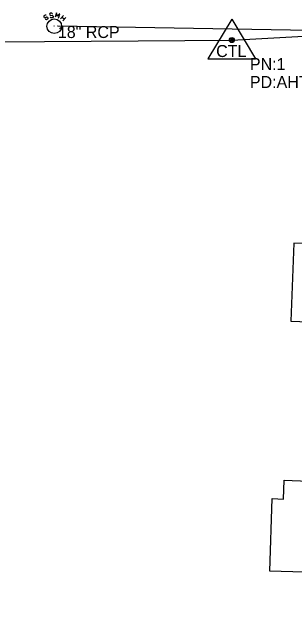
# Model space of a CAD drawing. Extents: x 1304270 to 1306561, y 1876019 to 1876752.
# Drawn here: x 1304782.1 to 1304900.2, y 1876151.4 to 1876403.7 of the extents above; entities that cross this region are included whole.
import ezdxf

# ---------------------------------------------------------------- set-up
doc = ezdxf.new("R2010")
doc.units = 0
for name, color, linetype in [('Default', 7, 'Continuous'), ('S_BUILDING', 7, 'Continuous'), ('S_PRIMARY_CTL', 7, 'Continuous'), ('S_PRIMARY_CTL_ANNOT', 7, 'Continuous'), ('S_SANITARY_SEWER', 7, 'Continuous'), ('S_STORM_SEWER', 7, 'Continuous'), ('S_STORM_SEWER_ANNOT', 7, 'Continuous'), ('S_UTL_PT_SYM', 7, 'Continuous')]:
    doc.layers.add(name, color=color, linetype=linetype)

msp = doc.modelspace()

# ---------------------------------------------------------------- linework, layer by layer
at = {"layer": 'Default'}
for p, q in [((1304873.94, 1876392.06), (1305473.53, 1876424.94)), ((1304280.48, 1876387.85), (1304873.94, 1876392.06))]:
    msp.add_line(p, q, dxfattribs=at)
at = {"layer": 'S_BUILDING'}
for points in [[(1304933.02, 1876306.02), (1304899.75, 1876307.28), (1304898.52, 1876274.75), (1304931.79, 1876273.49)], [(1304945.86, 1876210.45), (1304943.92, 1876151.39), (1304903.57, 1876152.71), (1304904.14, 1876170.05), (1304889.7, 1876170.52), (1304890.69, 1876200.72), (1304895.52, 1876200.56), (1304895.78, 1876208.37), (1304905.98, 1876208.03), (1304906.1, 1876211.75)]]:
    msp.add_lwpolyline(points, close=True, dxfattribs=at)
at = {"layer": 'S_PRIMARY_CTL'}
for p, q in [((1304873.94, 1876400.76), (1304863.91, 1876384.25)), ((1304873.94, 1876400.76), (1304883.77, 1876384.25)), ((1304863.91, 1876384.25), (1304883.77, 1876384.25))]:
    msp.add_line(p, q, dxfattribs=at)
for radius in [1.04, 0.609, 0.344]:
    msp.add_circle((1304873.94, 1876392.06), radius, dxfattribs=at)
at = {"layer": 'S_SANITARY_SEWER'}
for p, q in [((1304795.4, 1876402.12), (1304795.32, 1876401.73)), ((1304795.32, 1876401.73), (1304795.52, 1876401.46)), ((1304795.94, 1876402.51), (1304795.4, 1876402.12)), ((1304795.52, 1876401.46), (1304795.94, 1876401.35)), ((1304796.37, 1876402.43), (1304795.94, 1876402.51)), ((1304795.94, 1876401.35), (1304796.48, 1876401.69)), ((1304796.48, 1876400.53), (1304796.1, 1876400.61)), ((1304796.48, 1876401.69), (1304796.95, 1876401.62)), ((1304797.03, 1876400.92), (1304796.48, 1876400.53)), ((1304796.95, 1876401.62), (1304797.1, 1876401.35)), ((1304797.1, 1876401.35), (1304797.03, 1876400.92)), ((1304802.37, 1876400.88), (1304803.61, 1876402.35)), ((1304803.03, 1876401.66), (1304804, 1876400.84)), ((1304804.58, 1876401.54), (1304803.34, 1876400.07))]:
    msp.add_line(p, q, dxfattribs=at)
for points in [[(1304799.04, 1876403.05), (1304798.69, 1876403.32), (1304798.03, 1876403.24), (1304797.8, 1876402.9), (1304797.84, 1876402.59), (1304798.19, 1876402.28), (1304798.81, 1876402.39), (1304799.2, 1876402.08), (1304799.24, 1876401.77), (1304798.96, 1876401.38), (1304798.34, 1876401.31), (1304798, 1876401.58)], [(1304801.48, 1876401.19), (1304802.03, 1876403.05), (1304800.98, 1876402.04), (1304800.59, 1876403.48), (1304800.05, 1876401.62)]]:
    msp.add_lwpolyline(points, dxfattribs=at)
msp.add_circle((1304799.73, 1876397.82), 3.05, dxfattribs=at)
at = {"layer": 'S_STORM_SEWER'}
msp.add_line((1304960.46, 1876395.19), (1304801.23, 1876397.91), dxfattribs=at)
at = {"layer": 'S_UTL_PT_SYM'}
for points in [[(1304799.68, 1876397.93), (1304799.68, 1876397.98), (1304799.68, 1876397.93), (1304799.63, 1876397.93), (1304799.68, 1876397.93), (1304799.68, 1876397.88), (1304799.68, 1876397.93), (1304799.73, 1876397.93)], [(1304801.23, 1876397.91), (1304801.23, 1876397.96), (1304801.23, 1876397.91), (1304801.18, 1876397.91), (1304801.23, 1876397.91), (1304801.23, 1876397.86), (1304801.23, 1876397.91), (1304801.28, 1876397.91)]]:
    msp.add_lwpolyline(points, dxfattribs=at)

# ---------------------------------------------------------------- texts
at = {"layer": 'S_PRIMARY_CTL'}
msp.add_text('CTL', height=5, rotation=360, dxfattribs=at).set_placement((1304867.35, 1876384.98))
at = {"layer": 'S_PRIMARY_CTL_ANNOT'}
for s, p in [('PN:1', (1304881.44, 1876379.56)), ('PD:AHTD STD. MONUMENT STAMPED PN:1', (1304881.44, 1876372.06))]:
    msp.add_text(s, height=5, dxfattribs=at).set_placement(p)
at = {"layer": 'S_STORM_SEWER_ANNOT'}
msp.add_text('18" RCP', height=5, dxfattribs=at).set_placement((1304801.23, 1876392.91))

doc.saveas('drawing.dxf')
